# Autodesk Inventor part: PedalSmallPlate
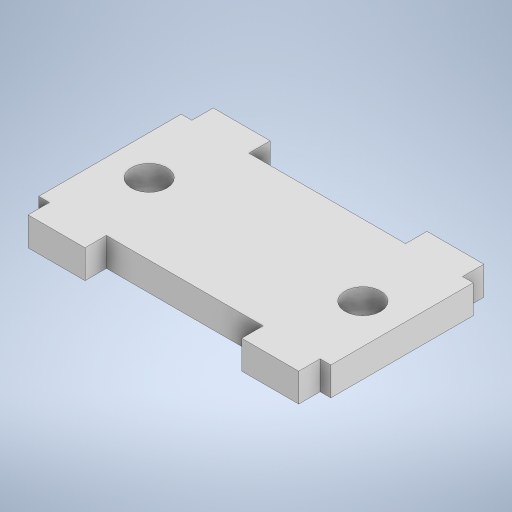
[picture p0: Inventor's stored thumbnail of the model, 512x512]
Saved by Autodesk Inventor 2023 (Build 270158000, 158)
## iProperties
Created: 2023-08
Part Number: PedalSmallPlate
Material: Generic
Document SubType Name: Modeling
Designer: Admin
Density: 1 g/cm^3
Appearance: Default
Author: Admin
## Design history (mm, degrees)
sketch "Sketch1"
  geometry: L1 (0, 0)-(41, 0); L2 (41, 0)-(41, -10); L3 (41, -10)-(0, -10); L4 (0, -10)-(0, 0); L5 (39.5, -10)-(31.5, -10); L6 (31.5, -10)-(31.5, -13); L7 (31.5, -13)-(39.5, -13); L8 (39.5, -13)-(39.5, -10); L9 (9.5, -10)-(1.5, -10); L10 (1.5, -10)-(1.5, -13); L11 (1.5, -13)-(9.5, -13); L12 (9.5, -13)-(9.5, -10); L13 (5.5, 0)-(5.5, -13); L14 (35.5, 0)-(35.5, -13); L15 (35.5, 0)-(41, 0); L16 (5.5, 0)-(0, 0); C1 r 2.5 at (5.5, 0); C2 r 2.5 at (35.5, 0); 6 further points
  constraints: 32 end point, 6 parallel, 4 point on line, 3 horizontal, 3 perpendicular, 2 centre point, 2 collinear, 2 midpoint, 2 vertical, 1 equal radius, 1 horizontal alignment
  dimensions: "d0" = 41 distance between parallel lines of L2 L4; "d1" = 10 distance between parallel lines of L3 L1; "d2" = 3 distance between parallel lines of L3 L7; "d3" = 5 diameter of C2; "d4" = 30 distance of L13.start L14.start; "d5" = 8 distance between parallel lines of L6 L8
extrude "Extrusion1" new body sketch "Sketch1" distance "d6" = 4; taper "d7" = 0 deg
mirror "Mirror1"
body "Solid1"
